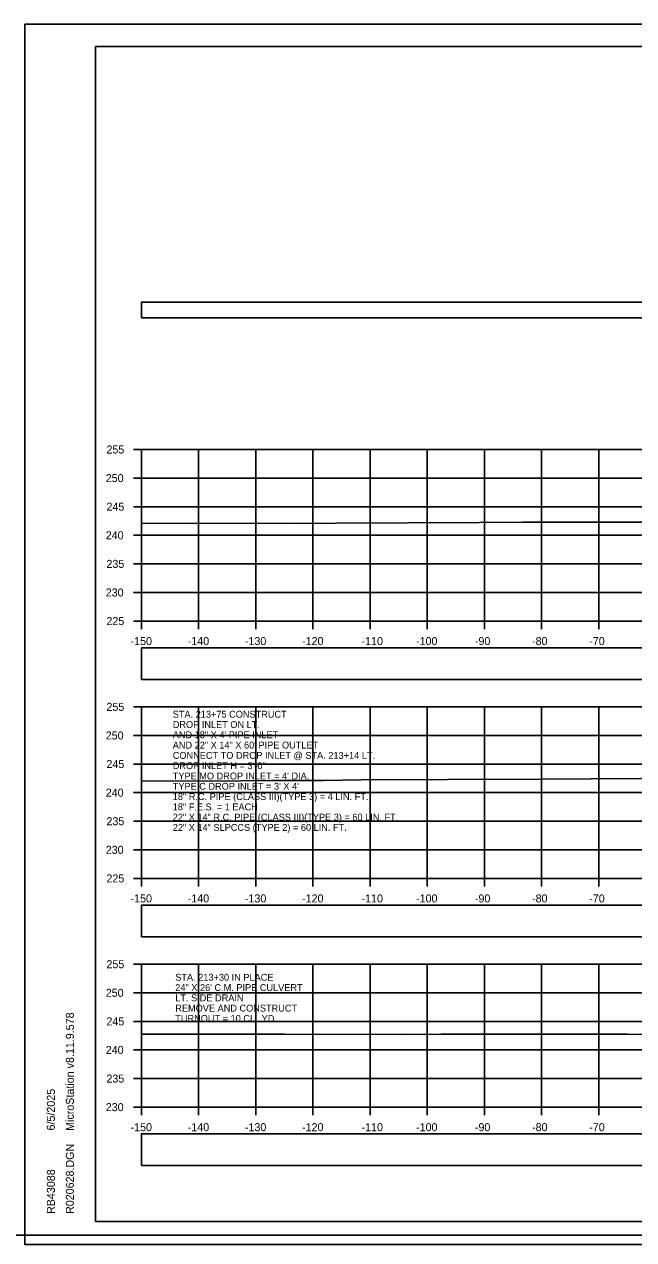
# Model space of a CAD drawing. Extents: x 1369627 to 1374022, y 380035 to 398173.
# Drawn here: x 1371928.1 to 1372034.6, y 383026.3 to 383238.8 of the extents above; entities that cross this region are included whole.
import ezdxf

# ---------------------------------------------------------------- set-up
doc = ezdxf.new("R2010")
doc.units = 0
for name, color, linetype in [('Default', 7, 'Continuous'), ('R_Axis', 7, 'Continuous'), ('R_Axis Annot', 7, 'Continuous'), ('R_Border', 7, 'Continuous'), ('R_Exist Surface', 7, 'Continuous'), ('R_Grid', 7, 'Continuous'), ('R_No Plot', 7, 'Continuous'), ('R_Water', 7, 'Continuous'), ('R_Water Annot', 7, 'Continuous')]:
    doc.layers.add(name, color=color, linetype=linetype)

msp = doc.modelspace()

# ---------------------------------------------------------------- linework, layer by layer
at = {"layer": 'Default'}
for points in [[(1371948.53, 383187.54), (1372248.53, 383187.54), (1372248.53, 383190.24), (1371948.53, 383190.24)], [(1371948.53, 383124.28), (1372248.53, 383124.28), (1372248.53, 383129.8), (1371948.53, 383129.8)], [(1371948.53, 383079.29), (1372248.53, 383079.29), (1372248.53, 383084.81), (1371948.53, 383084.81)], [(1371948.53, 383039.31), (1372248.53, 383039.31), (1372248.53, 383044.83), (1371948.53, 383044.83)]]:
    msp.add_lwpolyline(points, close=True, dxfattribs=at)
at = {"layer": 'R_Axis'}
for p, q in [((1371947.13, 383164.49), (1371948.53, 383164.49)), ((1371948.53, 383134.49), (1371948.53, 383164.49)), ((1371947.13, 383159.49), (1371948.53, 383159.49)), ((1371947.13, 383154.49), (1371948.53, 383154.49)), ((1371947.13, 383149.49), (1371948.53, 383149.49)), ((1371947.13, 383144.49), (1371948.53, 383144.49)), ((1371947.13, 383139.49), (1371948.53, 383139.49)), ((1371947.13, 383134.49), (1371948.53, 383134.49)), ((1371948.53, 383134.49), (1372248.53, 383134.49)), ((1371948.53, 383133.09), (1371948.53, 383134.49)), ((1371958.53, 383133.09), (1371958.53, 383134.49)), ((1371968.53, 383133.09), (1371968.53, 383134.49)), ((1371978.53, 383133.09), (1371978.53, 383134.49)), ((1371988.53, 383133.09), (1371988.53, 383134.49)), ((1371998.53, 383133.09), (1371998.53, 383134.49)), ((1372008.53, 383133.09), (1372008.53, 383134.49)), ((1372018.53, 383133.09), (1372018.53, 383134.49)), ((1372028.53, 383133.09), (1372028.53, 383134.49)), ((1371947.13, 383119.49), (1371948.53, 383119.49)), ((1371948.53, 383089.49), (1371948.53, 383119.49)), ((1371947.13, 383114.49), (1371948.53, 383114.49)), ((1371947.13, 383109.49), (1371948.53, 383109.49)), ((1371947.13, 383104.49), (1371948.53, 383104.49)), ((1371947.13, 383099.49), (1371948.53, 383099.49)), ((1371947.13, 383094.49), (1371948.53, 383094.49)), ((1371947.13, 383089.49), (1371948.53, 383089.49)), ((1371948.53, 383089.49), (1372248.53, 383089.49)), ((1371948.53, 383088.09), (1371948.53, 383089.49)), ((1371958.53, 383088.09), (1371958.53, 383089.49)), ((1371968.53, 383088.09), (1371968.53, 383089.49)), ((1371978.53, 383088.09), (1371978.53, 383089.49)), ((1371988.53, 383088.09), (1371988.53, 383089.49)), ((1371998.53, 383088.09), (1371998.53, 383089.49)), ((1372008.53, 383088.09), (1372008.53, 383089.49)), ((1372018.53, 383088.09), (1372018.53, 383089.49)), ((1372028.53, 383088.09), (1372028.53, 383089.49)), ((1371947.13, 383074.49), (1371948.53, 383074.49)), ((1371948.53, 383049.49), (1371948.53, 383074.49)), ((1371947.13, 383069.49), (1371948.53, 383069.49)), ((1371947.13, 383064.49), (1371948.53, 383064.49)), ((1371947.13, 383059.49), (1371948.53, 383059.49)), ((1371947.13, 383054.49), (1371948.53, 383054.49)), ((1371947.13, 383049.49), (1371948.53, 383049.49)), ((1371948.53, 383049.49), (1372248.53, 383049.49)), ((1371948.53, 383048.09), (1371948.53, 383049.49)), ((1371958.53, 383048.09), (1371958.53, 383049.49)), ((1371968.53, 383048.09), (1371968.53, 383049.49)), ((1371978.53, 383048.09), (1371978.53, 383049.49)), ((1371988.53, 383048.09), (1371988.53, 383049.49)), ((1371998.53, 383048.09), (1371998.53, 383049.49)), ((1372008.53, 383048.09), (1372008.53, 383049.49)), ((1372018.53, 383048.09), (1372018.53, 383049.49)), ((1372028.53, 383048.09), (1372028.53, 383049.49))]:
    msp.add_line(p, q, dxfattribs=at)
at = {"layer": 'R_Border'}
for p, q in [((1371940.53, 383234.95), (1372256.71, 383234.95)), ((1371940.53, 383029.49), (1371940.53, 383234.95)), ((1371940.53, 383029.49), (1371940.53, 383029.49)), ((1372256.71, 383029.49), (1371940.53, 383029.49))]:
    msp.add_line(p, q, dxfattribs=at)
at = {"layer": 'R_Exist Surface'}
for points in [[(1371948.53, 383151.59), (1371956.79, 383151.57), (1371974.2, 383151.58), (1371977.17, 383151.57), (1371982.56, 383151.62), (1372007.67, 383151.74), (1372015.27, 383151.77), (1372044.13, 383151.79)], [(1371948.53, 383106.54), (1371960.83, 383106.5), (1371971.17, 383106.6), (1371980.4, 383106.63), (1371986.98, 383106.73), (1372002.05, 383106.8), (1372018.52, 383106.86), (1372053.34, 383107.07)], [(1371948.53, 383062.26), (1371951.17, 383062.26), (1371952.84, 383062.26), (1371972.66, 383062.24), (1371973.53, 383062.25), (1371973.54, 383062.25), (1371994.78, 383062.22), (1371994.83, 383062.22), (1372000.97, 383062.23), (1372014, 383062.23), (1372014.16, 383062.23), (1372033.11, 383062.24), (1372033.51, 383062.24), (1372055.23, 383062.18)]]:
    msp.add_lwpolyline(points, dxfattribs=at)
at = {"layer": 'R_Grid'}
for p, q in [((1371948.53, 383164.49), (1372248.53, 383164.49)), ((1371948.53, 383134.49), (1371948.53, 383164.49)), ((1371958.53, 383134.49), (1371958.53, 383164.49)), ((1371968.53, 383134.49), (1371968.53, 383164.49)), ((1371978.53, 383134.49), (1371978.53, 383164.49)), ((1371988.53, 383134.49), (1371988.53, 383164.49)), ((1371998.53, 383134.49), (1371998.53, 383164.49)), ((1372008.53, 383134.49), (1372008.53, 383164.49)), ((1372018.53, 383134.49), (1372018.53, 383164.49)), ((1372028.53, 383134.49), (1372028.53, 383164.49)), ((1371948.53, 383159.49), (1372248.53, 383159.49)), ((1371948.53, 383154.49), (1372248.53, 383154.49)), ((1371948.53, 383149.49), (1372248.53, 383149.49)), ((1371948.53, 383144.49), (1372248.53, 383144.49)), ((1371948.53, 383139.49), (1372248.53, 383139.49)), ((1371948.53, 383134.49), (1372248.53, 383134.49)), ((1371948.53, 383119.49), (1372248.53, 383119.49)), ((1371948.53, 383089.49), (1371948.53, 383119.49)), ((1371958.53, 383089.49), (1371958.53, 383119.49)), ((1371968.53, 383089.49), (1371968.53, 383119.49)), ((1371978.53, 383089.49), (1371978.53, 383119.49)), ((1371988.53, 383089.49), (1371988.53, 383119.49)), ((1371998.53, 383089.49), (1371998.53, 383119.49)), ((1372008.53, 383089.49), (1372008.53, 383119.49)), ((1372018.53, 383089.49), (1372018.53, 383119.49)), ((1372028.53, 383089.49), (1372028.53, 383119.49)), ((1371948.53, 383114.49), (1372248.53, 383114.49)), ((1371948.53, 383109.49), (1372248.53, 383109.49)), ((1371948.53, 383104.49), (1372248.53, 383104.49)), ((1371948.53, 383099.49), (1372248.53, 383099.49)), ((1371948.53, 383094.49), (1372248.53, 383094.49)), ((1371948.53, 383089.49), (1372248.53, 383089.49)), ((1371948.53, 383074.49), (1372248.53, 383074.49)), ((1371948.53, 383049.49), (1371948.53, 383074.49)), ((1371958.53, 383049.49), (1371958.53, 383074.49)), ((1371968.53, 383049.49), (1371968.53, 383074.49)), ((1371978.53, 383049.49), (1371978.53, 383074.49)), ((1371988.53, 383049.49), (1371988.53, 383074.49)), ((1371998.53, 383049.49), (1371998.53, 383074.49)), ((1372008.53, 383049.49), (1372008.53, 383074.49)), ((1372018.53, 383049.49), (1372018.53, 383074.49)), ((1372028.53, 383049.49), (1372028.53, 383074.49)), ((1371948.53, 383069.49), (1372248.53, 383069.49)), ((1371948.53, 383064.49), (1372248.53, 383064.49)), ((1371948.53, 383059.49), (1372248.53, 383059.49)), ((1371948.53, 383054.49), (1372248.53, 383054.49)), ((1371948.53, 383049.49), (1372248.53, 383049.49))]:
    msp.add_line(p, q, dxfattribs=at)
at = {"layer": 'R_No Plot'}
for p, q in [((1371928.13, 383238.84), (1372261.46, 383238.84)), ((1371720.72, 383027.12), (1372533.33, 383027.12))]:
    msp.add_line(p, q, dxfattribs=at)
for points in [[(1371928.12, 383238.84), (1372261.46, 383238.84), (1372261.46, 383025.5), (1371928.12, 383025.5)], [(1372174.45, 383234.95), (1372194.07, 383234.95), (1372194.07, 383225.07), (1372210.18, 383225.07), (1372233.38, 383225.07), (1372233.38, 383192.4), (1372256.59, 383192.4), (1372256.71, 383029.49), (1371940.53, 383029.49), (1371940.53, 383234.95)]]:
    msp.add_lwpolyline(points, close=True, dxfattribs=at)

# ---------------------------------------------------------------- texts
at = {"layer": 'R_Axis Annot'}
for s, p in [('255', (1371942.42, 383163.79)), ('250', (1371942.3, 383158.79)), ('245', (1371942.42, 383153.79)), ('240', (1371942.3, 383148.79)), ('235', (1371942.42, 383143.79)), ('230', (1371942.3, 383138.79)), ('225', (1371942.42, 383133.79)), ('-150', (1371946.64, 383130.29)), ('-140', (1371956.64, 383130.29)), ('-130', (1371966.64, 383130.29)), ('-120', (1371976.64, 383130.29)), ('-110', (1371987.04, 383130.29)), ('-100', (1371996.58, 383130.29)), ('-90', (1372006.87, 383130.29)), ('-80', (1372016.87, 383130.29)), ('-70', (1372026.87, 383130.29)), ('255', (1371942.42, 383118.79)), ('250', (1371942.3, 383113.79)), ('245', (1371942.42, 383108.79)), ('240', (1371942.3, 383103.79)), ('235', (1371942.42, 383098.79)), ('230', (1371942.3, 383093.79)), ('225', (1371942.42, 383088.79)), ('-150', (1371946.64, 383085.29)), ('-140', (1371956.64, 383085.29)), ('-130', (1371966.64, 383085.29)), ('-120', (1371976.64, 383085.29)), ('-110', (1371987.04, 383085.29)), ('-100', (1371996.58, 383085.29)), ('-90', (1372006.87, 383085.29)), ('-80', (1372016.87, 383085.29)), ('-70', (1372026.87, 383085.29)), ('255', (1371942.42, 383073.79)), ('250', (1371942.3, 383068.79)), ('245', (1371942.42, 383063.79)), ('240', (1371942.3, 383058.79)), ('235', (1371942.42, 383053.79)), ('230', (1371942.3, 383048.79)), ('-150', (1371946.64, 383045.29)), ('-140', (1371956.64, 383045.29)), ('-130', (1371966.64, 383045.29)), ('-120', (1371976.64, 383045.29)), ('-110', (1371987.04, 383045.29)), ('-100', (1371996.58, 383045.29)), ('-90', (1372006.87, 383045.29)), ('-80', (1372016.87, 383045.29)), ('-70', (1372026.87, 383045.29))]:
    msp.add_text(s, height=1.4, dxfattribs=at).set_placement(p)
at = {"layer": 'R_Border'}
for s, p in [('MicroStation v8.11.9.578', (1371936.72, 383045.34)), ('6/5/2025', (1371933.4, 383045.41)), ('R020628.DGN', (1371936.72, 383030.81)), ('RB43088', (1371933.4, 383030.81))]:
    msp.add_text(s, height=1.4, rotation=90, dxfattribs=at).set_placement(p)
at = {"layer": 'R_Water'}
for s, p in [('STA. 213+30 IN PLACE', (1371954.46, 383071.6)), ('24" X 26\' C.M. PIPE CULVERT', (1371954.46, 383069.8)), ('LT. SIDE DRAIN', (1371954.46, 383068)), ('REMOVE AND CONSTRUCT', (1371954.46, 383066.2)), ('TURNOUT = 10 CU. YD.', (1371954.46, 383064.4))]:
    msp.add_text(s, height=1.2, dxfattribs=at).set_placement(p)
at = {"layer": 'R_Water Annot'}
for s, p in [('STA. 213+75 CONSTRUCT', (1371954.02, 383117.6)), ('DROP INLET ON LT.', (1371954.02, 383115.8)), ('AND 18" X 4\' PIPE INLET', (1371954.02, 383114)), ('AND 22" X 14" X 60\' PIPE OUTLET', (1371954.02, 383112.2)), ('CONNECT TO DROP INLET @ STA. 213+14 LT.', (1371954.02, 383110.4)), ('DROP INLET H = 3\'-0"', (1371954.02, 383108.6)), ("TYPE MO DROP INLET = 4' DIA.", (1371954.02, 383106.8)), ("TYPE C DROP INLET = 3' X 4'", (1371954.02, 383105)), ('18" R.C. PIPE (CLASS III)(TYPE 3) = 4 LIN. FT.', (1371954.02, 383103.2)), ('18" F.E.S. = 1 EACH', (1371954.02, 383101.4)), ('22" X 14" R.C. PIPE (CLASS III)(TYPE 3) = 60 LIN. FT.', (1371954.02, 383099.6)), ('22" X 14" SLPCCS (TYPE 2) = 60 LIN. FT.', (1371954.02, 383097.8))]:
    msp.add_text(s, height=1.2, dxfattribs=at).set_placement(p)

doc.saveas('drawing.dxf')
